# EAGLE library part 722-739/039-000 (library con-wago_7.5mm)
Serie 722, Federleiste mit Verriegelungsklinken / Series 722, Female connector with locking levers Polzahl / Pole No.: 9 Bemessungsspannung / Rated Voltage: 400 V Nennstrom / Nominal Current: 12 A Farbe / Color: xxxx / xxxx Stand: 01.01.2012. Die jeweils aktuellen Daten zu diesem Artikel finden Sie in unserem Produktkatalog, den Sie unter www.wago.com einsehen können. As of: 01/01/2012. Please find the newest data for this article in our product catalogue, which can be viewed under www.wago.com.
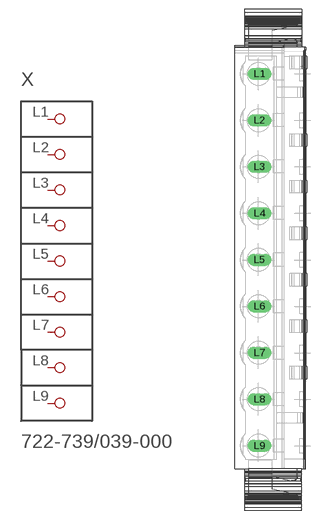
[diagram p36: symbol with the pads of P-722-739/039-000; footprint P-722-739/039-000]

Designator prefix X

## 722-739/039-000  [P-722-739/039-000]
L1  P1
L2  P2
L3  P3
L4  P4
L5  P5
L6  P6
L7  P7
L8  P8
L9  P9

## Footprint P-722-739/039-000 (pad centres in mm)
drill 1.3 long: L1 -2.159,30; L2 -2.159,22.5; L3 -2.159,15; L4 -2.159,7.5; L5 -2.159,0; L6 -2.159,-7.5; L7 -2.159,-15; L8 -2.159,-22.5; L9 -2.159,-30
